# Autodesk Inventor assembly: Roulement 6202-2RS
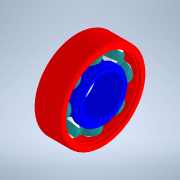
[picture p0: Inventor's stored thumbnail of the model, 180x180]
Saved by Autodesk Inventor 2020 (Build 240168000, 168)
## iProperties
Created: 2003-06
Part Number: Roulement 6202-2RS
Document SubType Name: Assembly
Designer: Bruno
Author: Bruno
Sending System: SolidWorks 2011
Last Author: Professeur
Last Saved: 2014-11-10
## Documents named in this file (5)
- D:\Téléchargements-2016-17\scoot_elec\pièces à assembler\ROULEMENT 6202-2RS\Roulement 6202-2RS.iam
- D:\Téléchargements-2016-17\scoot_elec\pièces à assembler\ROULEMENT 6202-2RS\Bague intérieure 6202-2RS.ipt
- D:\Téléchargements-2016-17\scoot_elec\pièces à assembler\ROULEMENT 6202-2RS\Cage 6202-2RS.ipt
- D:\Téléchargements-2016-17\scoot_elec\pièces à assembler\ROULEMENT 6202-2RS\Billes 6202-2RS.ipt
- D:\Téléchargements-2016-17\scoot_elec\pièces à assembler\ROULEMENT 6202-2RS\Bague extérieure 6202-2RS.iam
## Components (11 placed, 4 different names)
1. Bague intérieure 6202-2RS:1
2. Cage 6202-2RS:1
3. Billes 6202-2RS:1
4. Billes 6202-2RS:2
5. Billes 6202-2RS:3
6. Billes 6202-2RS:4
7. Billes 6202-2RS:5
8. Billes 6202-2RS:6
9. Billes 6202-2RS:7
10. Billes 6202-2RS:8
11. Bague extérieure 6202-2RS:1 [sub-assembly]
